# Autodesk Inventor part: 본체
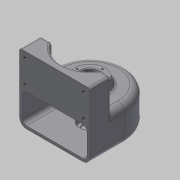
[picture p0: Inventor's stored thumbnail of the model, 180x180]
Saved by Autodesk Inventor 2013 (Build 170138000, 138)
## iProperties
Created: 2015-02
Part Number: 본체
Material: 일반
Document SubType Name: Modeling
Designer: Administrator
Density: 1 g/cm^3
Author: Administrator
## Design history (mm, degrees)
sketch "스케치1"
  geometry: L1 (50, 0)-(50, -50); L2 (50, -50)-(-50, -50); L3 (-50, -50)-(-50, 0); A1 r 50 centre (0, 0) between (50, 0) and (-50, 0); 1 further point
  constraints: 6 end point, 2 point on circle, 2 tangent, 1 centre point, 1 coincident, 1 parallel, 1 perpendicular, 1 vertical
  dimensions: "d0" = 100 diameter of A1; "d1" = 50 distance of L1.start L1.end
extrude "돌출1" new body sketch "스케치1" stored distance "d2" = 50; taper "d3" = 0 deg
sketch "스케치2"
  geometry: L1 (0, 25)-(0, 35); L2 (50, 25)-(0, 25) reference; L3 (0, 35)-(21.36, 35); L4 (21.36, 35)-(25, 25); L5 (25, 25)-(0, 25); 1 further point
  constraints: 8 end point, 1 collinear, 1 midpoint, 1 parallel, 1 vertical, 1 vertical alignment
  dimensions: "d4" = 10 distance of L1.start L1.end; "d5" = 110 deg angle of L2 L4
revolve "회전1" sketch "스케치2" stored, may be unused: angle "d6" = 90 deg
sketch "스케치3"
  geometry: C1 r 20 at (0, 0); A1 r 50 centre (0, 0) between (50, 0) and (-50, 0) reference
  constraints: 1 centre point, 1 coincident
  dimensions: "d7" = 40 diameter of C1
extrude "돌출2" join sketch "스케치3" distance "d8" = 9; taper "d9" = 0 deg
sketch "스케치4"
  geometry: L1 (-50, 0)-(-50, -50) reference; L2 (-50, -50)-(50, -50) reference; L3 (50, -50)-(50, 0) reference; L4 (50, -50)-(50, -20); L5 (50, -20)-(34.641, -20); L6 (-50, -50)-(-50, -20); L7 (-50, -20)-(-34.641, -20); L8 (-50, -50)-(50, -50); A1 r 50 centre (0, 0) between (50, 0) and (-50, 0) reference; A2 r 40 centre (0, 0) between (-34.641, -20) and (34.641, -20)
  constraints: 10 end point, 2 perpendicular, 2 point on circle, 2 point on line, 1 centre point, 1 coincident, 1 parallel
  dimensions: "d10" = 80 diameter of A2; "d11" = 30 distance of L2.end L4.end; "d12" = 30 distance of L1.end L6.end
extrude "돌출3" join sketch "스케치4" distance "d13" = 45; taper "d14" = 0 deg
sketch "스케치5"
  geometry: L1 (0, 21)-(0, -21); L2 (0, 21)-(46, 21); L3 (46, 21)-(46, -21); L4 (46, -21)-(0, -21); L5 (50, -25)-(50, 25) reference; 2 further points
  constraints: 8 end point, 2 perpendicular, 1 coincident, 1 midpoint, 1 parallel, 1 vertical
  dimensions: "d15" = 42 distance of L1.start L1.end; "d16" = 4 distance between parallel lines of L5 L3
revolve "회전2" sketch "스케치5" stored, may be unused: angle "d17" = 90 deg
sketch "스케치6"
  geometry: L1 (100, 0)-(0, 0) reference; L2 (4, 46)-(96, 46); L3 (96, 46)-(96, 4); L4 (96, 4)-(4, 4); L5 (4, 4)-(4, 46); 3 further points
  constraints: 8 end point, 2 midpoint, 2 parallel, 1 horizontal, 1 perpendicular, 1 vertical alignment
  dimensions: "d18" = 4 distance between parallel lines of L4 L1; "d19" = 42 distance of L2.end L3.end; "d20" = 92 distance between parallel lines of L5 L3
extrude "돌출4" cut sketch "스케치6" distance "d21" = 50; taper "d22" = 0 deg
sketch "스케치7"
  geometry: L1 (-21.36, 35)-(21.36, 35) reference; L2 (-20, -34)-(20, -34) reference; L3 (46, -21)-(0, -21) reference; L4 (0, 35)-(0, -34); L5 (0, 35)-(14, 35); L6 (14, 35)-(14, 25); L7 (14, 25)-(10, 25); L8 (10, 25)-(10, -21); L9 (10, -21)-(14, -21); L10 (14, -21)-(14, -29); L11 (14, -29)-(10, -29); L12 (10, -29)-(10, -31); L13 (10, -31)-(0, -31); 1 further point
  constraints: 20 end point, 7 perpendicular, 4 point on line, 2 midpoint
  dimensions: "d23" = 28 diameter of L6 L4; "d25" = 20 diameter of L8 L4; "d26" = 10 distance between parallel lines of L1 L7; "d27" = 28 diameter of L10 L4; "d29" = 8 distance between parallel lines of L11 L3; "d30" = 2 distance of L11.end L12.end; "d31" = 20 diameter of L12 L4
revolve "회전3" sketch "스케치7" stored, may be unused: angle "d32" = 90 deg
sketch "스케치8"
  geometry: C1 r 14 at (0, 0) reference; 1 further point
  constraints: 1 vertical alignment
  dimensions: "d33" = 18 distance of C1.centre point (0, 18)
hole "구멍1" sketch "스케치8" at (0, 18) diameter "d34" = 2.459; stored, may be unused: countersink angle "d38" = 90 deg, drill point angle "d40" = 118 deg; dims "d35" = 6, "d36" = 4, "d37" = 2, "d39" = 9
sketch "스케치9"
  geometry: L1 (0, 95)-(100, 95) reference; L2 (0, 0)-(0, 95) reference; 5 further points
  constraints: 2 horizontal alignment, 2 vertical alignment
  dimensions: "d44" = 33 distance of point (8.25, 53) point (8.25, 86); "d46" = 83.5 distance of point (91.75, 86) point (8.25, 86); "d47" = 9 distance from line of L1 point (8.25, 86); "d48" = 8.25 distance from line of L2 point (8.25, 86)
hole "구멍2" sketch "스케치9" at (8.25, 86), (8.25, 53), (91.75, 53), (91.75, 86) diameter "d49" = 5.134; stored, may be unused: countersink angle "d53" = 90 deg, drill point angle "d55" = 118 deg; dims "d50" = 10, "d51" = 4, "d52" = 2, "d54" = 13
node "작업 평면1"
sketch "스케치10"
  geometry: L1 (-50, -25)-(50, -25) reference; 2 further points
  constraints: 1 coincident, 1 other
  dimensions: "d56" = 25 distance from line of point (0, 0) L1
feature "엠보싱1" sketch "스케치10" dims "d0" = 100, "d1" = 50, "d57" = 0.5, "d58" = 0
chamfer "모따기1" distance "d59" = 1; stored, may be unused: second distance "d60" = 2, angle "d61" = 45 deg
fillet "모깎기1" dims "d62" = 0.3
fillet "모깎기2" dims "d63" = 6
fillet "모깎기5" dims "d66" = 10
fillet "모깎기6" dims "d67" = 3
fillet "모깎기7" dims "d68" = 3
fillet "모깎기8" dims "d69" = 3
node "솔리드1"
pattern_circular "원형 패턴1" dims angle "d42" = 360 deg
